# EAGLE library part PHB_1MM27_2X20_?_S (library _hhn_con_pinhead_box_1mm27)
Pin Header Box-Type, 1.27mm/0.5"/50mil Pitch, 2x20 Circuits, single gates in schematic Note: see library description for an important note about THT-version
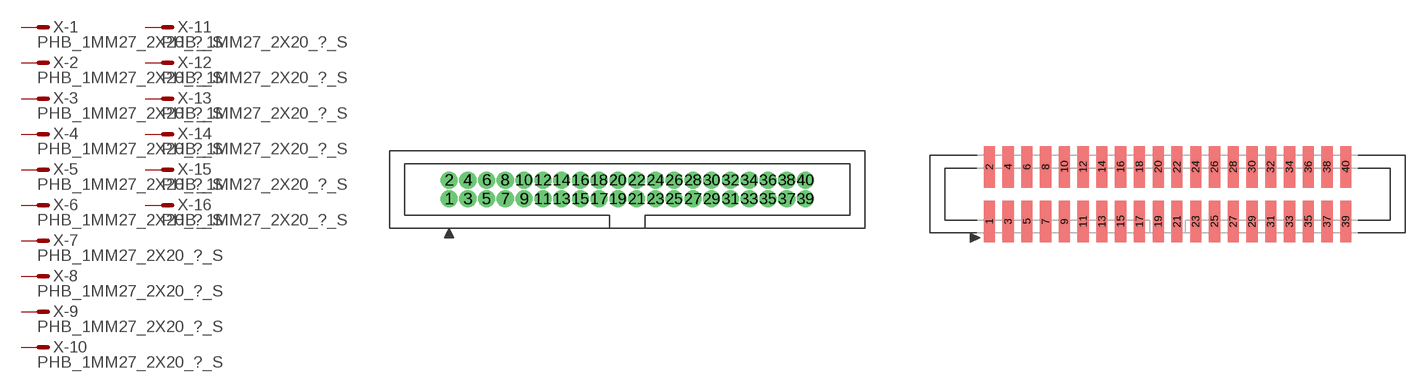
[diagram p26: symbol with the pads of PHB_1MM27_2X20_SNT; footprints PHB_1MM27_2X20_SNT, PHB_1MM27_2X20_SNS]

Designator prefix X; gates -1=M -2=M -3=M -4=M -5=M -6=M -7=M -8=M -9=M -10=M -11=M -12=M -13=M -14=M -15=M -16=M -17=M -18=M -19=M -20=M -21=M -22=M -23=M -24=M -25=M -26=M -27=M -28=M -29=M -30=M -31=M -32=M -33=M -34=M -35=M -36=M -37=M -38=M -39=M -40=M

## PHB_1MM27_2X20_SNT_S  [PHB_1MM27_2X20_SNT]
1  -1:S  pas
2  -2:S  pas
3  -3:S  pas
4  -4:S  pas
5  -5:S  pas
6  -6:S  pas
7  -7:S  pas
8  -8:S  pas
9  -9:S  pas
10  -10:S  pas
11  -11:S  pas
12  -12:S  pas
13  -13:S  pas
14  -14:S  pas
15  -15:S  pas
16  -16:S  pas
17  -17:S  pas
18  -18:S  pas
19  -19:S  pas
20  -20:S  pas
21  -21:S  pas
22  -22:S  pas
23  -23:S  pas
24  -24:S  pas
25  -25:S  pas
26  -26:S  pas
27  -27:S  pas
28  -28:S  pas
29  -29:S  pas
30  -30:S  pas
31  -31:S  pas
32  -32:S  pas
33  -33:S  pas
34  -34:S  pas
35  -35:S  pas
36  -36:S  pas
37  -37:S  pas
38  -38:S  pas
39  -39:S  pas
40  -40:S  pas

## PHB_1MM27_2X20_SNS_S  [PHB_1MM27_2X20_SNS]
Pads as for PHB_1MM27_2X20_SNT

## Footprint PHB_1MM27_2X20_SNT (pad centres in mm)
Pin Header Box-Type, 1.27mm Pitch, 2x20 circuits, Straight, No Locking, THT Important Note: Diameter in this lbr is set to a specific value (NOT 'auto' = 0), this is ignored by actual eagle versions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
drill 0.65 pad 1 round: 1 -12.065,-0.635; 2 -12.065,0.635; 3 -10.795,-0.635; 4 -10.795,0.635; 5 -9.525,-0.635; 6 -9.525,0.635; 7 -8.255,-0.635; 8 -8.255,0.635; 9 -6.985,-0.635; 10 -6.985,0.635; 11 -5.715,-0.635; 12 -5.715,0.635; 13 -4.445,-0.635; 14 -4.445,0.635; 15 -3.175,-0.635; 16 -3.175,0.635; 17 -1.905,-0.635; 18 -1.905,0.635; 19 -0.635,-0.635; 20 -0.635,0.635; 21 0.635,-0.635; 22 0.635,0.635; 23 1.905,-0.635; 24 1.905,0.635; 25 3.175,-0.635; 26 3.175,0.635; 27 4.445,-0.635; 28 4.445,0.635; 29 5.715,-0.635; 30 5.715,0.635; 31 6.985,-0.635; 32 6.985,0.635; 33 8.255,-0.635; 34 8.255,0.635; 35 9.525,-0.635; 36 9.525,0.635; 37 10.795,-0.635; 38 10.795,0.635; 39 12.065,-0.635; 40 12.065,0.635

## Footprint PHB_1MM27_2X20_SNS (pad centres in mm)
Pin Header Box-Type, 1.27mm Pitch, 2x20 circuits, Straight, No Locking, SMT
smd 0.76 x 2.8: 1 -12.065,-1.85; 2 -12.065,1.85; 3 -10.795,-1.85; 4 -10.795,1.85; 5 -9.525,-1.85; 6 -9.525,1.85; 7 -8.255,-1.85; 8 -8.255,1.85; 9 -6.985,-1.85; 10 -6.985,1.85; 11 -5.715,-1.85; 12 -5.715,1.85; 13 -4.445,-1.85; 14 -4.445,1.85; 15 -3.175,-1.85; 16 -3.175,1.85; 17 -1.905,-1.85; 18 -1.905,1.85; 19 -0.635,-1.85; 20 -0.635,1.85; 21 0.635,-1.85; 22 0.635,1.85; 23 1.905,-1.85; 24 1.905,1.85; 25 3.175,-1.85; 26 3.175,1.85; 27 4.445,-1.85; 28 4.445,1.85; 29 5.715,-1.85; 30 5.715,1.85; 31 6.985,-1.85; 32 6.985,1.85; 33 8.255,-1.85; 34 8.255,1.85; 35 9.525,-1.85; 36 9.525,1.85; 37 10.795,-1.85; 38 10.795,1.85; 39 12.065,-1.85; 40 12.065,1.85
